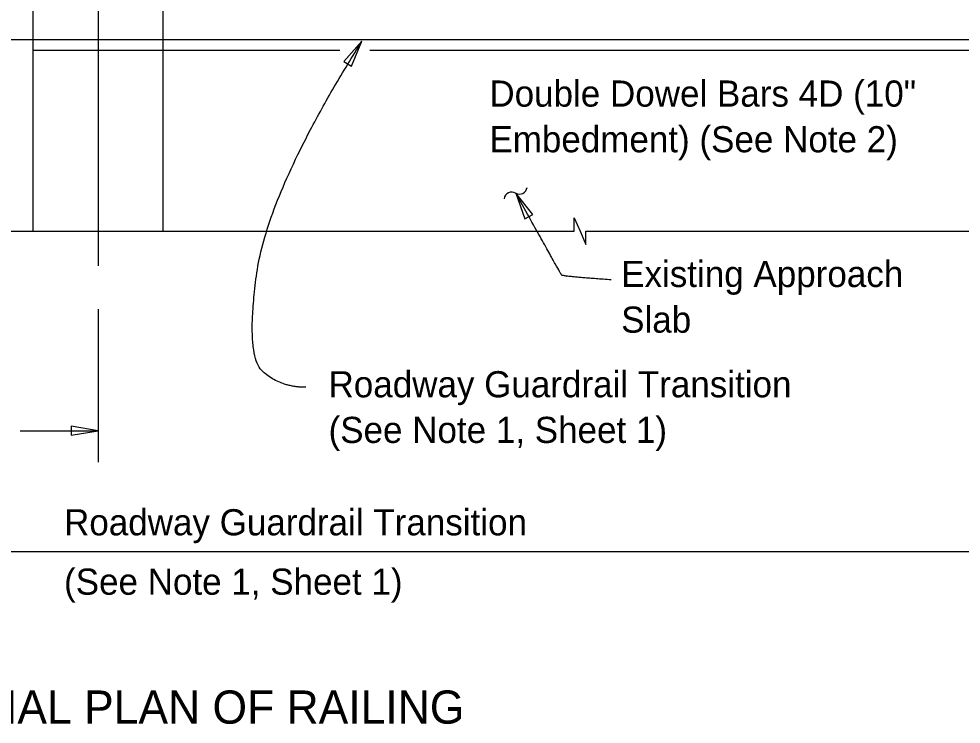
# Model space of a CAD drawing. Extents: x 0 to 41.1, y 0 to 25.9.
# Drawn here: x 27.57 to 34.83, y 14.11 to 19.55 of the extents above; entities that cross this region are included whole.
import ezdxf

# ---------------------------------------------------------------- set-up
doc = ezdxf.new("R2010")
doc.units = 0
for name, color, linetype in [('Dimension', 7, 'Continuous'), ('ExistSuperStruct', 7, 'Continuous'), ('Miscellaneous', 7, 'Continuous'), ('TextStructures', 7, 'Continuous')]:
    doc.layers.add(name, color=color, linetype=linetype)

msp = doc.modelspace()

# ---------------------------------------------------------------- linework, layer by layer
at = {"layer": 'Dimension'}
for p, q in [((28.1854, 20.1392), (28.1854, 17.6446)), ((28.1854, 17.3122), (28.1854, 16.1321)), ((27.5834, 16.3743), (28.1854, 16.3743))]:
    msp.add_line(p, q, dxfattribs=at)
for points in [[(30.2175, 19.3785), (30.0771, 19.2207), (30.1369, 19.1833)], [(31.4019, 18.2061), (31.4724, 18.007), (31.534, 18.0413)], [(28.1854, 16.3743), (27.9771, 16.4096), (27.9771, 16.3391)]]:
    msp.add_lwpolyline(points, close=True, dxfattribs=at)
for points in [[(26.9748, 17.9125), (31.853, 17.9125), (31.853, 18.0159), (31.898, 17.9125), (31.943, 17.8092), (31.943, 17.9125), (34.208, 17.9125)], [(34.208, 17.9125), (36.6599, 17.9125), (36.6599, 18.0159), (36.7049, 17.9125), (36.7499, 17.8092), (36.7499, 17.9125), (39.5571, 17.9125)], [(19.4255, 15.4425), (23.4976, 15.4425), (23.4976, 15.5459), (23.5426, 15.4425), (23.5876, 15.3392), (23.5876, 15.4425), (35.5208, 15.4425)]]:
    msp.add_lwpolyline(points, dxfattribs=at)
for centre, start, end in [((31.4307, 18.2576), 240.3192, 352.04642), ((31.3716, 18.154), 60.3192, 172.04642)]:
    msp.add_arc(centre, 0.0596, start, end, dxfattribs=at)
for points in [[(29.7858, 16.7091), (29.592, 16.7091), (29.3189, 16.947), (29.4951, 18.2244), (30.2175, 19.3785)], [(32.1368, 17.5373), (31.7636, 17.5637), (31.7482, 17.584), (31.4019, 18.2061)]]:
    msp.add_open_spline(points, degree=2, dxfattribs=at)
at = {"layer": 'ExistSuperStruct'}
for p, q in [((27.6854, 17.9125), (27.6854, 22.3785)), ((28.6854, 17.9125), (28.6854, 21.205)), ((27.6854, 19.3072), (30.0479, 19.3072)), ((30.277, 19.3072), (39.3809, 19.3072))]:
    msp.add_line(p, q, dxfattribs=at)
at = {"layer": 'Miscellaneous'}
msp.add_line((26.2319, 19.3905), (39.6173, 19.3905), dxfattribs=at)

# ---------------------------------------------------------------- texts
at = {"layer": 'Dimension'}
for s, p in [('Double Dowel Bars 4D (10" ', (31.1988, 18.8725)), ('Embedment) (See Note 2)', (31.1988, 18.5205)), ('Existing Approach ', (32.214, 17.4821)), ('Slab', (32.214, 17.1301)), ('Roadway Guardrail Transition ', (29.96, 16.6319)), ('(See Note 1, Sheet 1)', (29.96, 16.2799)), ('Roadway Guardrail Transition', (27.9225, 15.5679)), ('(See Note 1, Sheet 1)', (27.9225, 15.1103))]:
    msp.add_text(s, height=0.2016, dxfattribs=at).set_placement(p)
at = {"layer": 'TextStructures'}
msp.add_text('PARTIAL PLAN OF RAILING', height=0.256001, dxfattribs=at).set_placement((26.5547, 14.1161))

doc.saveas('drawing.dxf')
